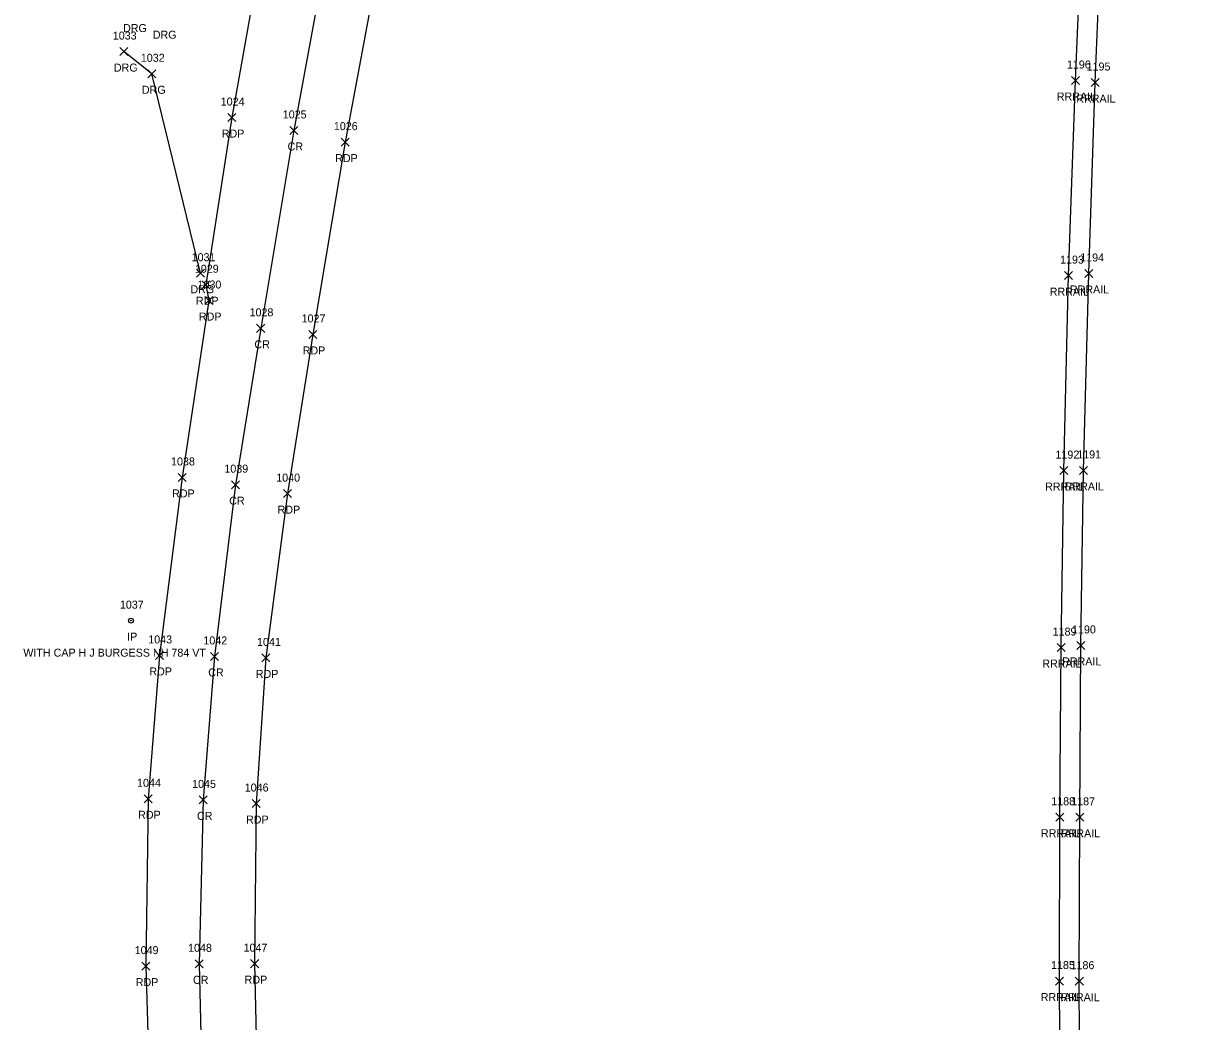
# Model space of a CAD drawing. Extents: x 1754529 to 1755810, y 621660 to 624656.
# Drawn here: x 1755345.3 to 1755636.7, y 623160.6 to 623410 of the extents above; entities that cross this region are included whole.
import ezdxf

# ---------------------------------------------------------------- set-up
doc = ezdxf.new("R2010")
doc.units = 0
for name, color, linetype in [('Level 14', 7, 'Continuous'), ('M_A', 7, 'Continuous'), ('M_C', 7, 'Continuous'), ('M_I', 7, 'Continuous'), ('MPIR', 7, 'Continuous'), ('P_A', 7, 'Continuous'), ('P_I', 7, 'Continuous'), ('PET', 7, 'Continuous'), ('PRC', 7, 'Continuous'), ('R_A', 7, 'Continuous'), ('R_I', 7, 'Continuous'), ('R_TIC', 7, 'Continuous'), ('RDG', 7, 'Continuous'), ('RR', 7, 'Continuous')]:
    doc.layers.add(name, color=color, linetype=linetype)

msp = doc.modelspace()

# ---------------------------------------------------------------- linework, layer by layer
at = {"layer": 'Level 14'}
for points in [[(1755396.43, 623385.49), (1755398.43, 623387.49)], [(1755398.43, 623385.49), (1755396.43, 623387.49)], [(1755411.93, 623382.28), (1755413.93, 623384.28)], [(1755413.93, 623382.28), (1755411.93, 623384.28)], [(1755424.75, 623379.35), (1755426.75, 623381.35)], [(1755426.75, 623379.35), (1755424.75, 623381.35)], [(1755389.98, 623343.71), (1755391.98, 623345.71)], [(1755391.98, 623343.71), (1755389.98, 623345.71)], [(1755390.72, 623339.77), (1755392.72, 623341.77)], [(1755392.72, 623339.77), (1755390.72, 623341.77)], [(1755403.64, 623332.82), (1755405.64, 623334.82)], [(1755405.64, 623332.82), (1755403.64, 623334.82)], [(1755416.64, 623331.29), (1755418.64, 623333.29)], [(1755418.64, 623331.29), (1755416.64, 623333.29)], [(1755384.02, 623295.56), (1755386.02, 623297.56)], [(1755386.02, 623295.56), (1755384.02, 623297.56)], [(1755397.35, 623293.75), (1755399.35, 623295.75)], [(1755399.35, 623293.75), (1755397.35, 623295.75)], [(1755410.38, 623291.51), (1755412.38, 623293.51)], [(1755412.38, 623291.51), (1755410.38, 623293.51)], [(1755378.33, 623251.08), (1755380.33, 623253.08)], [(1755380.33, 623251.08), (1755378.33, 623253.08)], [(1755392.11, 623250.83), (1755394.11, 623252.83)], [(1755394.11, 623250.83), (1755392.11, 623252.83)], [(1755404.94, 623250.45), (1755406.94, 623252.45)], [(1755406.94, 623250.45), (1755404.94, 623252.45)], [(1755375.53, 623215.25), (1755377.53, 623217.25)], [(1755377.53, 623215.25), (1755375.53, 623217.25)], [(1755389.3, 623214.98), (1755391.3, 623216.98)], [(1755391.3, 623214.98), (1755389.3, 623216.98)], [(1755402.49, 623214.07), (1755404.49, 623216.07)], [(1755404.49, 623214.07), (1755402.49, 623216.07)], [(1755374.95, 623173.43), (1755376.95, 623175.43)], [(1755376.95, 623173.43), (1755374.95, 623175.43)], [(1755388.28, 623174.01), (1755390.28, 623176.01)], [(1755390.28, 623174.01), (1755388.28, 623176.01)], [(1755402.14, 623174.05), (1755404.14, 623176.05)], [(1755404.14, 623174.05), (1755402.14, 623176.05)]]:
    msp.add_lwpolyline(points, dxfattribs=at)
at = {"layer": 'MPIR'}
for radius in [0.625, 0.0833]:
    msp.add_circle((1755372.24, 623260.77), radius, dxfattribs=at)
at = {"layer": 'PET'}
for points in [[(1755535.07, 624132.59), (1755507.27, 623983.72), (1755476.9, 623815.46), (1755460.3, 623719.87), (1755437.79, 623591.8), (1755421.36, 623504.45), (1755418.26, 623495.73), (1755404.2, 623424.5), (1755397.43, 623386.49), (1755390.98, 623344.71), (1755391.72, 623340.77), (1755385.02, 623296.56), (1755379.33, 623252.08), (1755376.53, 623216.25), (1755375.95, 623174.43), (1755377.19, 623132.58)], [(1755561.91, 624125.77), (1755533.66, 623976.91), (1755504.04, 623811.48), (1755486.8, 623713.65), (1755464.22, 623587.1), (1755446.31, 623490.47), (1755433.28, 623420.6), (1755425.75, 623380.35), (1755417.64, 623332.29), (1755411.38, 623292.51), (1755405.94, 623251.45), (1755403.49, 623215.07), (1755403.14, 623175.05), (1755404.1, 623131.29)]]:
    msp.add_lwpolyline(points, dxfattribs=at)
at = {"layer": 'PRC'}
msp.add_lwpolyline([(1755548.82, 624129.6), (1755520.89, 623980.45), (1755490.93, 623813.93), (1755473.47, 623716.78), (1755450.77, 623588.43), (1755432.8, 623492.49), (1755420.05, 623422.21), (1755412.93, 623383.28), (1755404.64, 623333.82), (1755398.35, 623294.75), (1755393.11, 623251.83), (1755390.3, 623215.98), (1755389.28, 623175.01), (1755390.29, 623132.74)], dxfattribs=at)
at = {"layer": 'R_TIC'}
for points in [[(1755369.47, 623401.98), (1755371.47, 623403.98)], [(1755371.47, 623401.98), (1755369.47, 623403.98)], [(1755376.47, 623396.43), (1755378.47, 623398.43)], [(1755378.47, 623396.43), (1755376.47, 623398.43)], [(1755607.24, 623394.75), (1755609.24, 623396.75)], [(1755609.24, 623394.75), (1755607.24, 623396.75)], [(1755612.11, 623394.25), (1755614.11, 623396.25)], [(1755614.11, 623394.25), (1755612.11, 623396.25)], [(1755388.61, 623346.59), (1755390.61, 623348.59)], [(1755390.61, 623346.59), (1755388.61, 623348.59)], [(1755605.47, 623345.99), (1755607.47, 623347.99)], [(1755607.47, 623345.99), (1755605.47, 623347.99)], [(1755610.51, 623346.53), (1755612.51, 623348.53)], [(1755612.51, 623346.53), (1755610.51, 623348.53)], [(1755604.32, 623297.27), (1755606.32, 623299.27)], [(1755606.32, 623297.27), (1755604.32, 623299.27)], [(1755609.19, 623297.31), (1755611.19, 623299.31)], [(1755611.19, 623297.31), (1755609.19, 623299.31)], [(1755603.62, 623253.04), (1755605.62, 623255.04)], [(1755605.62, 623253.04), (1755603.62, 623255.04)], [(1755608.56, 623253.58), (1755610.56, 623255.58)], [(1755610.56, 623253.58), (1755608.56, 623255.58)], [(1755603.28, 623210.65), (1755605.28, 623212.65)], [(1755605.28, 623210.65), (1755603.28, 623212.65)], [(1755608.26, 623210.62), (1755610.26, 623212.62)], [(1755610.26, 623210.62), (1755608.26, 623212.62)], [(1755603.22, 623169.71), (1755605.22, 623171.71)], [(1755605.22, 623169.71), (1755603.22, 623171.71)], [(1755608.16, 623169.67), (1755610.16, 623171.67)], [(1755610.16, 623169.67), (1755608.16, 623171.67)]]:
    msp.add_lwpolyline(points, dxfattribs=at)
at = {"layer": 'RDG'}
msp.add_lwpolyline([(1755389.61, 623347.59), (1755377.47, 623397.43), (1755370.47, 623402.98)], dxfattribs=at)
at = {"layer": 'RR'}
for points in [[(1755604.49, 623127.28), (1755604.22, 623170.71), (1755604.28, 623211.65), (1755604.62, 623254.04), (1755605.32, 623298.27), (1755606.47, 623346.99), (1755608.24, 623395.75), (1755610.2, 623442.91), (1755612.83, 623494.78), (1755615.55, 623540.26), (1755618.38, 623584.4), (1755619.97, 623606.74), (1755623.67, 623654.94), (1755627.39, 623699.11), (1755631.78, 623745.19)], [(1755609.4, 623127.16), (1755609.16, 623170.67), (1755609.26, 623211.62), (1755609.56, 623254.58), (1755610.19, 623298.31), (1755611.51, 623347.53), (1755613.11, 623395.25), (1755615.13, 623443.29), (1755620.46, 623540.5), (1755623.35, 623584.17), (1755624.97, 623606.26), (1755628.57, 623654.98), (1755632.43, 623698.79), (1755636.73, 623745.2)]]:
    msp.add_lwpolyline(points, dxfattribs=at)

# ---------------------------------------------------------------- texts
at = {"layer": 'M_A'}
msp.add_text('IP', height=2, dxfattribs=at).set_placement((1755371.29, 623255.77))
at = {"layer": 'M_C'}
msp.add_text('WITH CAP H J BURGESS NH 784 VT', height=2, dxfattribs=at).set_placement((1755345.34, 623251.77))
at = {"layer": 'M_I'}
msp.add_text('1037', height=2, dxfattribs=at).set_placement((1755369.47, 623263.77))
at = {"layer": 'P_A'}
for s, p in [('RDP', (1755394.92, 623381.49)), ('CR', (1755411.36, 623378.28)), ('RDP', (1755423.24, 623375.35)), ('RDP', (1755388.47, 623339.71)), ('RDP', (1755389.21, 623335.77)), ('CR', (1755403.08, 623328.82)), ('RDP', (1755415.13, 623327.29)), ('RDP', (1755382.51, 623291.56)), ('CR', (1755396.78, 623289.75)), ('RDP', (1755408.87, 623287.51)), ('RDP', (1755376.82, 623247.08)), ('CR', (1755391.54, 623246.83)), ('RDP', (1755403.42, 623246.45)), ('RDP', (1755374.02, 623211.25)), ('CR', (1755388.73, 623210.98)), ('RDP', (1755400.97, 623210.07)), ('RDP', (1755373.44, 623169.43)), ('CR', (1755387.72, 623170.01)), ('RDP', (1755400.63, 623170.05))]:
    msp.add_text(s, height=2, dxfattribs=at).set_placement(p)
at = {"layer": 'P_I'}
for s, p in [('1024', (1755394.66, 623389.49)), ('1025', (1755410.16, 623386.28)), ('1026', (1755422.92, 623383.35)), ('1029', (1755388.2, 623347.71)), ('1030', (1755388.86, 623343.77)), ('1028', (1755401.87, 623336.82)), ('1027', (1755414.87, 623335.29)), ('1038', (1755382.25, 623299.56)), ('1039', (1755395.57, 623297.75)), ('1040', (1755408.53, 623295.51)), ('1043', (1755376.56, 623255.08)), ('1042', (1755390.33, 623254.83)), ('1041', (1755403.73, 623254.45)), ('1044', (1755373.76, 623219.25)), ('1045', (1755387.52, 623218.98)), ('1046', (1755400.66, 623218.07)), ('1047', (1755400.37, 623178.05)), ('1049', (1755373.17, 623177.43)), ('1048', (1755386.51, 623178.01))]:
    msp.add_text(s, height=2, dxfattribs=at).set_placement(p)
at = {"layer": 'R_A'}
for s, p in [('DRG', (1755370.26, 623407.86)), ('DRG', (1755377.68, 623406.2)), ('DRG', (1755367.96, 623397.98)), ('DRG', (1755374.96, 623392.43)), ('RRRAIL', (1755603.53, 623390.75)), ('RRRAIL', (1755608.4, 623390.25)), ('DRG', (1755387.09, 623342.59)), ('RRRAIL', (1755601.76, 623341.99)), ('RRRAIL', (1755606.8, 623342.53)), ('RRRAIL', (1755600.61, 623293.27)), ('RRRAIL', (1755605.49, 623293.31)), ('RRRAIL', (1755599.91, 623249.04)), ('RRRAIL', (1755604.85, 623249.58)), ('RRRAIL', (1755599.57, 623206.65)), ('RRRAIL', (1755604.55, 623206.62)), ('RRRAIL', (1755599.51, 623165.71)), ('RRRAIL', (1755604.45, 623165.67))]:
    msp.add_text(s, height=2, dxfattribs=at).set_placement(p)
at = {"layer": 'R_I'}
for s, p in [('1033', (1755367.7, 623405.98)), ('1032', (1755374.7, 623400.43)), ('1196', (1755606.06, 623398.75)), ('1195', (1755610.98, 623398.25)), ('1031', (1755387.4, 623350.59)), ('1193', (1755604.35, 623349.99)), ('1194', (1755609.38, 623350.53)), ('1192', (1755603.19, 623301.27)), ('1191', (1755608.64, 623301.31)), ('1189', (1755602.49, 623257.04)), ('1190', (1755607.34, 623257.58)), ('1188', (1755602.15, 623214.65)), ('1187', (1755607.13, 623214.62)), ('1185', (1755602.09, 623173.71)), ('1186', (1755606.97, 623173.67))]:
    msp.add_text(s, height=2, dxfattribs=at).set_placement(p)

doc.saveas('drawing.dxf')
